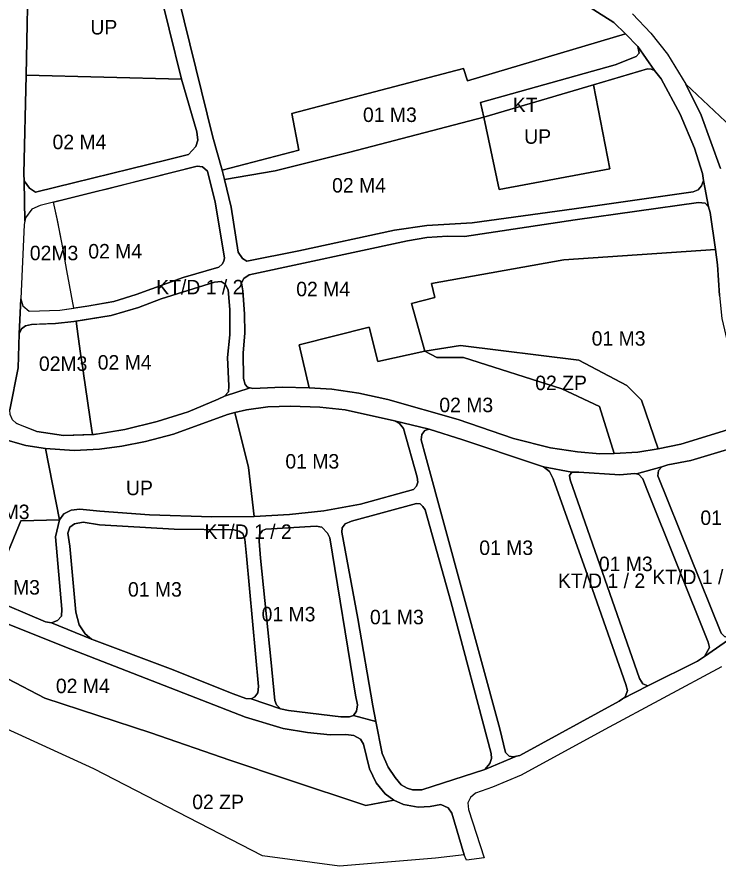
# Model space of a CAD drawing. Extents: x 7419295 to 7421535, y 5544294 to 5545394.
# Drawn here: x 7420728 to 7421212, y 5544294 to 5544881 of the extents above; entities that cross this region are included whole.
import ezdxf

# ---------------------------------------------------------------- set-up
doc = ezdxf.new("R2010")
doc.units = 0
doc.layers.add('linie_rozgraniczajace', color=7, linetype='Continuous')
doc.layers.add('oznaczenia_przeznaczen', color=7, linetype='Continuous')

msp = doc.modelspace()

# ---------------------------------------------------------------- linework, layer by layer
at = {"layer": 'linie_rozgraniczajace'}
for points in [[(7421061.62, 5544927.02), (7421140.55, 5544876.74), (7421148.51, 5544869.05), (7421039.36, 5544836.44), (7421036.78, 5544844.98), (7420918.13, 5544813.95), (7420922.97, 5544788.66), (7420870.05, 5544774.81), (7420863.55, 5544797.65), (7420835.98, 5544909.83)], [(7421213.44, 5544688.32), (7421212.1, 5544709.5), (7421210.76, 5544720.11), (7421206.94, 5544745.55), (7421205.8, 5544749.6), (7421202.48, 5544767.72), (7421201.64, 5544772.61), (7421196.16, 5544790.12), (7421186.15, 5544813.57), (7421173.24, 5544837.94), (7421168.56, 5544843.56), (7421157.14, 5544860.15), (7421148.51, 5544869.05), (7421140.55, 5544876.74), (7421061.62, 5544927.02)], [(7420736.48, 5544922.57), (7420734.86, 5544840.45), (7420733.25, 5544772.37), (7420733.45, 5544767.38), (7420733.85, 5544739.66), (7420733.37, 5544737.39), (7420731.04, 5544686), (7420730.05, 5544661.76), (7420729.31, 5544638.3), (7420723.57, 5544609.33)], [(7420835.98, 5544909.83), (7420863.55, 5544797.65), (7420870.05, 5544774.81), (7420871.69, 5544768.35), (7420876.28, 5544749.31), (7420881.04, 5544718.2), (7420884.08, 5544713.85), (7420887.02, 5544712.03), (7420922.91, 5544719.13), (7420989.1, 5544733.3), (7421011.47, 5544736.73), (7421042.72, 5544738.45), (7421112.98, 5544748.14), (7421195.16, 5544759.97), (7421198.6, 5544761.3), (7421201.04, 5544763.94), (7421202.48, 5544767.72), (7421205.8, 5544749.6), (7421203.52, 5544752.01), (7421199.01, 5544752.62), (7421113.84, 5544740.54), (7421037.29, 5544729.13), (7421025.64, 5544729.34), (7421011.37, 5544728.3), (7420997.98, 5544726.06), (7420888.65, 5544702.65), (7420884.99, 5544700.11), (7420883.54, 5544696.98), (7420884.25, 5544691.43), (7420885.62, 5544675.68), (7420885.79, 5544662.38), (7420884.54, 5544648.73), (7420884.9, 5544630.89), (7420885.91, 5544626.95), (7420887.68, 5544625.09), (7420889.47, 5544624.54), (7420871.68, 5544618.87), (7420874.36, 5544621.71), (7420874.81, 5544625.87), (7420873.78, 5544645.39), (7420875.32, 5544661.14), (7420875.46, 5544678.66), (7420874.3, 5544692.25), (7420872.21, 5544696.04), (7420869.33, 5544698.08), (7420864.75, 5544697.55), (7420827.98, 5544685.94), (7420812.34, 5544679.96), (7420793.4, 5544674.53), (7420767.61, 5544670.3), (7420754.99, 5544668.92), (7420738.4, 5544668.36), (7420734.43, 5544667.4), (7420731.6, 5544665.35), (7420730.05, 5544661.76), (7420731.04, 5544686), (7420732.58, 5544681.2), (7420736.76, 5544677.59), (7420758.03, 5544678.28), (7420776.74, 5544680.84), (7420795.41, 5544684.11), (7420810.77, 5544688.88), (7420843.1, 5544700.81), (7420867.76, 5544707.93), (7420870.18, 5544709.83), (7420871.24, 5544712.03), (7420871.73, 5544714.21), (7420865.37, 5544752.83), (7420859.89, 5544774.21), (7420856.51, 5544777.13), (7420852.84, 5544777.7), (7420800.03, 5544764.22), (7420744.36, 5544750.44), (7420738.7, 5544747.87), (7420734.34, 5544741.93), (7420733.85, 5544739.66), (7420733.45, 5544767.38), (7420737.05, 5544762.52), (7420741.29, 5544759.74), (7420833.06, 5544782.11), (7420846.75, 5544785.63), (7420851.86, 5544791.29), (7420853.39, 5544795.45), (7420852.67, 5544801.33), (7420841.97, 5544837.75), (7420825.09, 5544906.9)], [(7421153.3, 5544882.68), (7421165.92, 5544869.47), (7421177.47, 5544855.04), (7421190.2, 5544834.12), (7421200.76, 5544812.79), (7421214.02, 5544775.92)], [(7421214.02, 5544775.92), (7421200.76, 5544812.79), (7421190.2, 5544834.12), (7421233.16, 5544793.69)], [(7420727.82, 5544600.06), (7420742.24, 5544594.51), (7420760.67, 5544591.73), (7420781.74, 5544592.35), (7420802.83, 5544595.71), (7420825.22, 5544601.29), (7420846.65, 5544608.07), (7420867.29, 5544616.64), (7420871.68, 5544618.87), (7420889.47, 5544624.54), (7420891.25, 5544623.98), (7420911.49, 5544625), (7420930.06, 5544624.62), (7420945.74, 5544623.66), (7420964.41, 5544620.9), (7420984.36, 5544616.59), (7421033.07, 5544602.79), (7421071.2, 5544589.66), (7421096.64, 5544583.22), (7421115.44, 5544580.34), (7421130.78, 5544578.91), (7421140.63, 5544579.3), (7421157.09, 5544580.09), (7421170.98, 5544582.34), (7421186.73, 5544585.6), (7421218.96, 5544595.55)], [(7421241.15, 5544588.74), (7421193.57, 5544574.43), (7421177.84, 5544571.46), (7421173.61, 5544569.95), (7421156.21, 5544565.11), (7421154.76, 5544565.42), (7421144.63, 5544564.56), (7421116.26, 5544566.39), (7421111.49, 5544566.35), (7421091.84, 5544569.94), (7421085.7, 5544571.97), (7421036.2, 5544588.64), (7421013.1, 5544596.01), (7420989.14, 5544601.83), (7420954.99, 5544609.31), (7420937.58, 5544611.11), (7420917.28, 5544611.99), (7420901.71, 5544611.37), (7420886.99, 5544609.29), (7420878.82, 5544607.48), (7420873.69, 5544606.13), (7420836.45, 5544592.58), (7420817.25, 5544587.48), (7420800.89, 5544584.2), (7420785.44, 5544582.21), (7420768.01, 5544581.38), (7420748.03, 5544582.62), (7420734.48, 5544584.68), (7420722.45, 5544588.18)], [(7421037.09, 5544302.2), (7421028.68, 5544330.81), (7421026.15, 5544334.44), (7421020.97, 5544336.76), (7421013.71, 5544335.42), (7421005.3, 5544335.08), (7420995.22, 5544336.76), (7420988.63, 5544339.74), (7420982.72, 5544344.24), (7420976.37, 5544351.74), (7420971.85, 5544361.39), (7420967.66, 5544378.52), (7420965.61, 5544382.01), (7420961.05, 5544384.51), (7420955.46, 5544385.18), (7420944.66, 5544385.04), (7420929.02, 5544386.49), (7420912.21, 5544389.38), (7420886.15, 5544397.12), (7420765.57, 5544444.2), (7420681.96, 5544477.58)], [(7420681.96, 5544477.58), (7420765.57, 5544444.2), (7420886.15, 5544397.12), (7420912.21, 5544389.38), (7420929.02, 5544386.49), (7420944.66, 5544385.04), (7420955.46, 5544385.18), (7420961.05, 5544384.51), (7420965.61, 5544382.01), (7420967.66, 5544378.52), (7420971.85, 5544361.39), (7420976.37, 5544351.74), (7420982.72, 5544344.24), (7420988.63, 5544339.74), (7420969.38, 5544336.28), (7420915.14, 5544354.02), (7420875.33, 5544367.46), (7420820.92, 5544386.38), (7420747.77, 5544410.39), (7420722.04, 5544423.59)], [(7420709.11, 5544479.54), (7420748.11, 5544463.04), (7420752.39, 5544462.19), (7420779.97, 5544450.96), (7420834.49, 5544430.43), (7420877.76, 5544413.31), (7420886.5, 5544410.13), (7420890.15, 5544409.83), (7420910.43, 5544402.93), (7420915.81, 5544401.67), (7420952.02, 5544397.34), (7420958.08, 5544397.36), (7420960.83, 5544398.38), (7420976.24, 5544394.13), (7420980.6, 5544372.18), (7420984.75, 5544362.57), (7420989.53, 5544355.48), (7420993.61, 5544350.53), (7420997.83, 5544348.08), (7421001.39, 5544346.98), (7421007.82, 5544347.01), (7421051.41, 5544361.07), (7421073.33, 5544370.23), (7421075.68, 5544370.78), (7421144.25, 5544408.09), (7421146.36, 5544409.83), (7421163.87, 5544418.9), (7421198.32, 5544435.8), (7421203.12, 5544438.98), (7421221.82, 5544452.13)], [(7421214.78, 5544431.88), (7421134.24, 5544388.56), (7421076.47, 5544357.22), (7421056.63, 5544348.81), (7421044.88, 5544344.61), (7421041.5, 5544341.79), (7421039.74, 5544337.99), (7421040.09, 5544333.38), (7421050.85, 5544300.07), (7421038.67, 5544298.53), (7421037.09, 5544302.2)]]:
    msp.add_lwpolyline(points, dxfattribs=at)
for points in [[(7420736.48, 5544922.57), (7420824.13, 5544917.18), (7420825.09, 5544906.9), (7420841.97, 5544837.75), (7420734.86, 5544840.45)], [(7421148.51, 5544869.05), (7421157.14, 5544860.15), (7421157.96, 5544855.72), (7421155.83, 5544853.24), (7421141.28, 5544847.59), (7421048.39, 5544821.54), (7421050.62, 5544811.5), (7420958.14, 5544787.18), (7420906.74, 5544774.4), (7420871.69, 5544768.35), (7420870.05, 5544774.81), (7420922.97, 5544788.66), (7420918.13, 5544813.95), (7421036.78, 5544844.98), (7421039.36, 5544836.44)], [(7421157.14, 5544860.15), (7421168.56, 5544843.56), (7421166.29, 5544844.67), (7421163.74, 5544844.71), (7421126.35, 5544833.8), (7421050.62, 5544811.5), (7421048.39, 5544821.54), (7421141.28, 5544847.59), (7421155.83, 5544853.24), (7421157.96, 5544855.72)], [(7421126.35, 5544833.8), (7421163.74, 5544844.71), (7421166.29, 5544844.67), (7421168.56, 5544843.56), (7421173.24, 5544837.94), (7421186.15, 5544813.57), (7421196.16, 5544790.12), (7421201.64, 5544772.61), (7421202.48, 5544767.72), (7421201.04, 5544763.94), (7421198.6, 5544761.3), (7421195.16, 5544759.97), (7421112.98, 5544748.14), (7421042.72, 5544738.45), (7421011.47, 5544736.73), (7420989.1, 5544733.3), (7420922.91, 5544719.13), (7420887.02, 5544712.03), (7420884.08, 5544713.85), (7420881.04, 5544718.2), (7420876.28, 5544749.31), (7420871.69, 5544768.35), (7420906.74, 5544774.4), (7420958.14, 5544787.18), (7421050.62, 5544811.5), (7421061.32, 5544761.39), (7421137.67, 5544775.82)], [(7420734.86, 5544840.45), (7420841.97, 5544837.75), (7420852.67, 5544801.33), (7420853.39, 5544795.45), (7420851.86, 5544791.29), (7420846.75, 5544785.63), (7420833.06, 5544782.11), (7420741.29, 5544759.74), (7420737.05, 5544762.52), (7420733.45, 5544767.38), (7420733.25, 5544772.37)], [(7421126.35, 5544833.8), (7421137.67, 5544775.82), (7421061.32, 5544761.39), (7421050.62, 5544811.5)], [(7420753.7, 5544752.75), (7420785.84, 5544760.7), (7420791, 5544761.98), (7420797.19, 5544763.51), (7420807.02, 5544766), (7420852.84, 5544777.7), (7420856.51, 5544777.13), (7420859.89, 5544774.21), (7420865.37, 5544752.83), (7420871.73, 5544714.21), (7420871.24, 5544712.03), (7420870.18, 5544709.83), (7420867.76, 5544707.93), (7420843.1, 5544700.81), (7420810.77, 5544688.88), (7420795.41, 5544684.11), (7420777.04, 5544680.89), (7420767.77, 5544679.61), (7420762.92, 5544705.6), (7420759.71, 5544723.69), (7420756.27, 5544741.24)], [(7420732.58, 5544681.2), (7420736.76, 5544677.59), (7420758.03, 5544678.28), (7420767.77, 5544679.61), (7420762.92, 5544705.6), (7420759.71, 5544723.69), (7420756.5, 5544740.22), (7420753.7, 5544752.75), (7420744.36, 5544750.44), (7420738.7, 5544747.87), (7420734.34, 5544741.93), (7420733.85, 5544739.66), (7420733.37, 5544737.39), (7420731.04, 5544686)], [(7420889.47, 5544624.54), (7420887.68, 5544625.09), (7420885.91, 5544626.95), (7420884.9, 5544630.89), (7420884.54, 5544648.73), (7420885.79, 5544662.38), (7420885.62, 5544675.68), (7420884.25, 5544691.43), (7420883.54, 5544696.98), (7420884.99, 5544700.11), (7420888.65, 5544702.65), (7420997.98, 5544726.06), (7421011.37, 5544728.3), (7421025.64, 5544729.34), (7421037.29, 5544729.13), (7421113.84, 5544740.54), (7421199.01, 5544752.62), (7421203.52, 5544752.01), (7421205.8, 5544749.6), (7421206.94, 5544745.55), (7421210.76, 5544720.11), (7421105.89, 5544713.01), (7421014.51, 5544696.59), (7421016.84, 5544686.9), (7421000.75, 5544682.83), (7421009.98, 5544649.77), (7420977.54, 5544642.81), (7420971.61, 5544666.46), (7420923.28, 5544654.26), (7420930.06, 5544624.62), (7420911.49, 5544625), (7420891.25, 5544623.98)], [(7421210.76, 5544720.11), (7421212.1, 5544709.5), (7421213.44, 5544688.32), (7421215.06, 5544672.35), (7421219.45, 5544653.87), (7421228.5, 5544628.12), (7421237.43, 5544611.2), (7421238.34, 5544606.8), (7421236.91, 5544603.1), (7421234.34, 5544600.61), (7421218.96, 5544595.55), (7421186.73, 5544585.6), (7421170.98, 5544582.34), (7421159.54, 5544616.11), (7421149.43, 5544626.06), (7421116.42, 5544643.66), (7421034.62, 5544653.87), (7421009.98, 5544649.77), (7421000.75, 5544682.83), (7421016.84, 5544686.9), (7421014.51, 5544696.59), (7421105.89, 5544713.01)], [(7420812.34, 5544679.96), (7420827.98, 5544685.94), (7420864.75, 5544697.55), (7420869.33, 5544698.08), (7420872.21, 5544696.04), (7420874.3, 5544692.25), (7420875.46, 5544678.66), (7420875.32, 5544661.14), (7420873.78, 5544645.39), (7420874.81, 5544625.87), (7420874.36, 5544621.71), (7420871.68, 5544618.87), (7420867.29, 5544616.64), (7420846.65, 5544608.07), (7420825.22, 5544601.29), (7420802.83, 5544595.71), (7420785.03, 5544592.88), (7420780.62, 5544592.32), (7420780.19, 5544595.04), (7420774.32, 5544634.42), (7420774.03, 5544636.54), (7420772.41, 5544648.31), (7420770.8, 5544660.04), (7420769.36, 5544670.59), (7420793.4, 5544674.53)], [(7420729.8, 5544599.3), (7420727.82, 5544600.06), (7420725.42, 5544602.47), (7420723.82, 5544606.16), (7420723.57, 5544609.33), (7420729.31, 5544638.3), (7420730.05, 5544661.76), (7420730.83, 5544663.56), (7420731.6, 5544665.35), (7420734.43, 5544667.4), (7420738.4, 5544668.36), (7420742.14, 5544668.48), (7420754.99, 5544668.92), (7420767.61, 5544670.3), (7420769.36, 5544670.59), (7420770.8, 5544660.04), (7420772.41, 5544648.31), (7420774.03, 5544636.54), (7420774.32, 5544634.42), (7420780.19, 5544595.04), (7420780.62, 5544592.32), (7420760.67, 5544591.73), (7420742.24, 5544594.51)], [(7420977.54, 5544642.81), (7421009.98, 5544649.77), (7421018.35, 5544645.4), (7421036.78, 5544645.58), (7421104.66, 5544623.91), (7421130.5, 5544611.76), (7421140.63, 5544579.3), (7421130.78, 5544578.91), (7421115.44, 5544580.34), (7421096.64, 5544583.22), (7421071.2, 5544589.66), (7421033.07, 5544602.79), (7420984.36, 5544616.59), (7420964.41, 5544620.9), (7420945.74, 5544623.66), (7420930.06, 5544624.62), (7420923.28, 5544654.26), (7420971.61, 5544666.46)], [(7421009.98, 5544649.77), (7421034.62, 5544653.87), (7421116.42, 5544643.66), (7421149.43, 5544626.06), (7421159.54, 5544616.11), (7421170.98, 5544582.34), (7421157.09, 5544580.09), (7421140.63, 5544579.3), (7421130.5, 5544611.76), (7421104.66, 5544623.91), (7421036.78, 5544645.58), (7421018.35, 5544645.4)], [(7420878.82, 5544607.48), (7420886.99, 5544609.29), (7420901.71, 5544611.37), (7420917.28, 5544611.99), (7420937.58, 5544611.11), (7420954.99, 5544609.31), (7420989.14, 5544601.83), (7420992.61, 5544599.92), (7420995.18, 5544596.38), (7421004.67, 5544562.87), (7421005.18, 5544559.5), (7421004.33, 5544556.62), (7421002.12, 5544554.26), (7420965.53, 5544544.13), (7420940.28, 5544539.56), (7420916.61, 5544537.12), (7420892.28, 5544535.8), (7420888.25, 5544569.53)], [(7420878.82, 5544607.48), (7420888.25, 5544569.53), (7420892.28, 5544535.8), (7420862.97, 5544535.42), (7420820.02, 5544536.86), (7420785.71, 5544539.44), (7420771.83, 5544540.81), (7420765.8, 5544540), (7420760.81, 5544537.52), (7420757.7, 5544533.42), (7420748.03, 5544582.62), (7420768.01, 5544581.38), (7420785.44, 5544582.21), (7420800.89, 5544584.2), (7420817.25, 5544587.48), (7420836.45, 5544592.58), (7420873.69, 5544606.13)], [(7420989.14, 5544601.83), (7421013.1, 5544596.01), (7421010.1, 5544595.09), (7421008.03, 5544592.28), (7421007.57, 5544588.73), (7421010.44, 5544577.51), (7421061.83, 5544389.1), (7421065.77, 5544372.77), (7421068.18, 5544370.14), (7421070.99, 5544369.68), (7421073.33, 5544370.23), (7421051.41, 5544361.07), (7421054.76, 5544365.07), (7421056.07, 5544368.65), (7421055.69, 5544372.01), (7421027.94, 5544477.01), (7421010.33, 5544540.23), (7421008.65, 5544542.66), (7421006.88, 5544544.52), (7421004.32, 5544544.76), (7420959.27, 5544532.47), (7420954.98, 5544530.59), (7420952.91, 5544527.78), (7420952.78, 5544524.82), (7420963.76, 5544465.29), (7420974.08, 5544405), (7420976.24, 5544394.13), (7420960.83, 5544398.38), (7420962.78, 5544401.19), (7420963.44, 5544405.76), (7420962.2, 5544412.43), (7420944.46, 5544521.06), (7420942.75, 5544524.29), (7420938.95, 5544528.23), (7420935.03, 5544529.09), (7420900.31, 5544527), (7420897.92, 5544526), (7420895.98, 5544522.96), (7420895.67, 5544518.74), (7420896.64, 5544506.84), (7420903.7, 5544437.3), (7420906.43, 5544408.68), (7420907.64, 5544405.77), (7420910.43, 5544402.93), (7420890.15, 5544409.83), (7420892.76, 5544411.19), (7420894.83, 5544414), (7420895.26, 5544418.34), (7420887, 5544508.45), (7420885.8, 5544520.01), (7420884.43, 5544523.93), (7420881.94, 5544525.65), (7420878.15, 5544526.41), (7420837.06, 5544527), (7420785.39, 5544529.91), (7420774.16, 5544531.73), (7420768.26, 5544530.69), (7420764.96, 5544528.28), (7420763.67, 5544524.13), (7420764.89, 5544515.2), (7420769.14, 5544469.75), (7420771.33, 5544460.85), (7420775.57, 5544454.77), (7420779.97, 5544450.96), (7420752.39, 5544462.19), (7420756.45, 5544463.83), (7420759.11, 5544466.9), (7420759.52, 5544471.69), (7420754.93, 5544521.74), (7420757.7, 5544533.42), (7420760.81, 5544537.52), (7420765.8, 5544540), (7420771.83, 5544540.81), (7420785.71, 5544539.44), (7420820.02, 5544536.86), (7420862.97, 5544535.42), (7420892.28, 5544535.8), (7420916.61, 5544537.12), (7420940.28, 5544539.56), (7420965.53, 5544544.13), (7421002.12, 5544554.26), (7421004.33, 5544556.62), (7421005.18, 5544559.5), (7421004.67, 5544562.87), (7420995.18, 5544596.38), (7420992.61, 5544599.92)], [(7421013.1, 5544596.01), (7421036.2, 5544588.64), (7421085.7, 5544571.97), (7421091.84, 5544569.94), (7421096.1, 5544566.7), (7421098.48, 5544561.79), (7421121.07, 5544498.41), (7421148.76, 5544419.65), (7421149.9, 5544415.49), (7421148.48, 5544411.56), (7421146.36, 5544409.83), (7421144.25, 5544408.09), (7421075.68, 5544370.78), (7421073.33, 5544370.23), (7421070.99, 5544369.68), (7421068.18, 5544370.14), (7421065.77, 5544372.77), (7421061.83, 5544389.1), (7421010.44, 5544577.51), (7421007.57, 5544588.73), (7421008.03, 5544592.28), (7421010.1, 5544595.09)], [(7420709.11, 5544479.54), (7420680.94, 5544490.34), (7420677.76, 5544493.96), (7420675.74, 5544499), (7420676.93, 5544505.53), (7420681.32, 5544522.77), (7420688.09, 5544541.39), (7420705.31, 5544574.17), (7420713.96, 5544585.33), (7420718.1, 5544587.89), (7420722.45, 5544588.18), (7420734.48, 5544584.68), (7420748.03, 5544582.62), (7420757.7, 5544533.42), (7420731.09, 5544532.76)], [(7421173.61, 5544569.95), (7421177.84, 5544571.46), (7421193.57, 5544574.43), (7421241.15, 5544588.74), (7421244.82, 5544588.44), (7421248.25, 5544586.19), (7421251.11, 5544582.43), (7421283.44, 5544514.42), (7421284.37, 5544510.95), (7421283.93, 5544506.16), (7421280.78, 5544501.56), (7421223.48, 5544452.42), (7421221.82, 5544452.13), (7421220.16, 5544451.84), (7421216.79, 5544452.75), (7421214.51, 5544455.18), (7421170.83, 5544563.87), (7421171.32, 5544567.47)], [(7421091.84, 5544569.94), (7421111.49, 5544566.35), (7421109.83, 5544564.05), (7421110.44, 5544560.94), (7421158.27, 5544423.89), (7421160.48, 5544420.25), (7421163.87, 5544418.9), (7421146.36, 5544409.83), (7421148.48, 5544411.56), (7421149.9, 5544415.49), (7421148.76, 5544419.65), (7421121.07, 5544498.41), (7421098.48, 5544561.79), (7421096.1, 5544566.7)], [(7421173.61, 5544569.95), (7421171.32, 5544567.47), (7421170.83, 5544563.87), (7421214.51, 5544455.18), (7421216.79, 5544452.75), (7421220.16, 5544451.84), (7421221.82, 5544452.13), (7421203.12, 5544438.98), (7421206.52, 5544445.23), (7421205.58, 5544449), (7421163.14, 5544554.61), (7421160.48, 5544561.63), (7421157.65, 5544564.79), (7421156.21, 5544565.11)], [(7421111.49, 5544566.35), (7421116.26, 5544566.39), (7421144.63, 5544564.56), (7421154.76, 5544565.42), (7421156.21, 5544565.11), (7421157.65, 5544564.79), (7421160.48, 5544561.63), (7421163.14, 5544554.61), (7421205.58, 5544449), (7421206.52, 5544445.23), (7421203.12, 5544438.98), (7421198.32, 5544435.8), (7421163.87, 5544418.9), (7421160.48, 5544420.25), (7421158.27, 5544423.89), (7421110.44, 5544560.94), (7421109.83, 5544564.05)], [(7420976.24, 5544394.13), (7420974.08, 5544405), (7420963.76, 5544465.29), (7420952.78, 5544524.82), (7420952.91, 5544527.78), (7420954.98, 5544530.59), (7420959.27, 5544532.47), (7421004.32, 5544544.76), (7421006.88, 5544544.52), (7421008.65, 5544542.66), (7421010.33, 5544540.23), (7421027.94, 5544477.01), (7421055.69, 5544372.01), (7421056.07, 5544368.65), (7421054.76, 5544365.07), (7421051.41, 5544361.07), (7421007.82, 5544347.01), (7421001.39, 5544346.98), (7420997.83, 5544348.08), (7420993.61, 5544350.53), (7420989.53, 5544355.48), (7420984.75, 5544362.57), (7420980.6, 5544372.18)], [(7420709.11, 5544479.54), (7420731.09, 5544532.76), (7420757.7, 5544533.42), (7420754.93, 5544521.74), (7420759.52, 5544471.69), (7420759.11, 5544466.9), (7420756.45, 5544463.83), (7420752.39, 5544462.19), (7420748.11, 5544463.04)], [(7420779.97, 5544450.96), (7420775.57, 5544454.77), (7420771.33, 5544460.85), (7420769.14, 5544469.75), (7420764.89, 5544515.2), (7420763.67, 5544524.13), (7420764.96, 5544528.28), (7420768.26, 5544530.69), (7420774.16, 5544531.73), (7420785.39, 5544529.91), (7420837.06, 5544527), (7420878.15, 5544526.41), (7420881.94, 5544525.65), (7420884.43, 5544523.93), (7420885.8, 5544520.01), (7420887, 5544508.45), (7420895.26, 5544418.34), (7420894.83, 5544414), (7420892.76, 5544411.19), (7420890.15, 5544409.83), (7420886.5, 5544410.13), (7420877.76, 5544413.31), (7420834.49, 5544430.43)], [(7420910.43, 5544402.93), (7420907.64, 5544405.77), (7420906.43, 5544408.68), (7420903.7, 5544437.3), (7420896.64, 5544506.84), (7420895.67, 5544518.74), (7420895.98, 5544522.96), (7420897.92, 5544526), (7420900.31, 5544527), (7420935.03, 5544529.09), (7420938.95, 5544528.23), (7420942.75, 5544524.29), (7420944.46, 5544521.06), (7420962.2, 5544412.43), (7420963.44, 5544405.76), (7420962.78, 5544401.19), (7420960.83, 5544398.38), (7420958.08, 5544397.36), (7420952.02, 5544397.34), (7420915.81, 5544401.67)], [(7420670.12, 5544449.36), (7420692.2, 5544438.03), (7420722.04, 5544423.59), (7420747.77, 5544410.39), (7420820.92, 5544386.38), (7420875.33, 5544367.46), (7420915.14, 5544354.02), (7420969.38, 5544336.28), (7420988.63, 5544339.74), (7420995.22, 5544336.76), (7421005.3, 5544335.08), (7421013.71, 5544335.42), (7421020.97, 5544336.76), (7421026.15, 5544334.44), (7421028.68, 5544330.81), (7421037.09, 5544302.2), (7421017.41, 5544299.9), (7420951.2, 5544294.38), (7420897.99, 5544301.46), (7420781.41, 5544361.51), (7420710, 5544394.09), (7420665.8, 5544413.78)]]:
    msp.add_lwpolyline(points, close=True, dxfattribs=at)

# ---------------------------------------------------------------- texts
at = {"layer": 'oznaczenia_przeznaczen'}
for s, p in [('UP', (7420779.13, 5544868.53)), ('KT', (7421070.74, 5544814.93)), ('01 M3', (7420967.3, 5544808.1)), ('02 M4', (7420753.01, 5544789.33)), ('UP', (7421078.58, 5544793.05)), ('02 M4', (7420945.98, 5544759.38)), ('02M3', (7420737.32, 5544712.65)), ('02 M4', (7420777.68, 5544713.86)), ('KT/D 1 / 2', (7420824.56, 5544689.1)), ('02 M4', (7420921.23, 5544687.77)), ('01 M3', (7421125.18, 5544653.66)), ('02M3', (7420743.61, 5544636.26)), ('02 M4', (7420784.19, 5544637.14)), ('02 ZP', (7421086.21, 5544622.95)), ('02 M3', (7421020, 5544607.74)), ('01 M3', (7420913.72, 5544568.82)), ('UP', (7420803.71, 5544550.43)), ('02 M3', (7420699.95, 5544533.9)), ('01 M3', (7421200.21, 5544529.86)), ('KT/D 1 / 2', (7420857.93, 5544520.23)), ('01 M3', (7421047.58, 5544509.15)), ('01 M3', (7421130.15, 5544497.99)), ('KT/D 1 / 2', (7421167.05, 5544488.99)), ('KT/D 1 / 2', (7421101.89, 5544486.35)), ('01 M3', (7420707.12, 5544481.81)), ('01 M3', (7420805.08, 5544480.38)), ('01 M3', (7420897.32, 5544463.3)), ('01 M3', (7420972.11, 5544461.29)), ('02 M4', (7420755.32, 5544413.73)), ('02 ZP', (7420849.45, 5544333.65))]:
    msp.add_text(s, height=10, dxfattribs=at).set_placement(p)

doc.saveas('drawing.dxf')
